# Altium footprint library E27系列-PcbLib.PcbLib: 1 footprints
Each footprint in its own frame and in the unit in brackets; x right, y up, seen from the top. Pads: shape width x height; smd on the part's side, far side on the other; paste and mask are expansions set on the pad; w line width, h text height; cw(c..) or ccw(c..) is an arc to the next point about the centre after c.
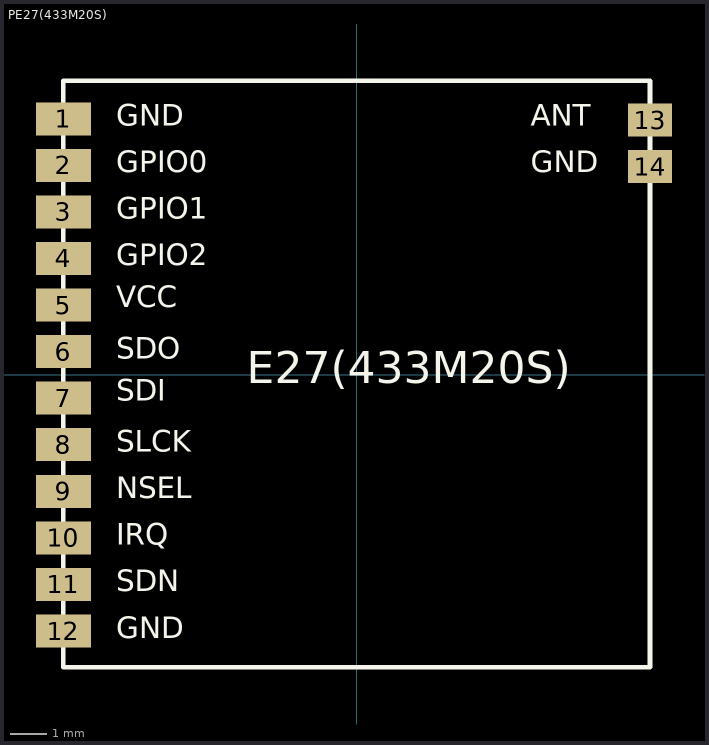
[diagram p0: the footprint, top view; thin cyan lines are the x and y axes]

## PE27(433M20S) [mm] "16mm*16mm*2.0mm-S"
pads (14):
  rect 1.5x0.9 smd: 1(-8.002,6.985) 2(-8.002,5.715) 3(-8.002,4.445) 4(-8.002,3.175) 5(-8.002,1.905) 6(-8.002,0.635) 7(-8.002,-0.635) 8(-8.002,-1.905) 9(-8.002,-3.175) 10(-8.002,-4.445) 11(-8.002,-5.715) 12(-8.002,-6.985)
  rect 1.2x0.9 smd: 13(8.002,6.947) 14(8.002,5.677)
Top Overlay:
  lines w0.127: -8.002,-7.976 7.998,-7.976 7.998,8.024 -8.002,8.024 -8.002,-7.976
  text "E27(433M20S)" at -3.005,-0.509 h1.5
  text "GND" at 4.742,5.333 h1
  text "ANT" at 4.742,6.603 h1
  text "GND" at -6.561,-7.367 h1
  text "SDI" at -6.561,-0.89 h1
  text "SDO" at -6.561,0.253 h1
  text "VCC" at -6.561,1.65 h1
  text "GPIO2" at -6.561,2.793 h1
  text "GPIO1" at -6.561,4.063 h1
  text "GND" at -6.561,6.603 h1
  text "GPIO0" at -6.561,5.333 h1
  text "SLCK" at -6.561,-2.287 h1
  text "NSEL" at -6.561,-3.557 h1
  text "IRQ" at -6.561,-4.827 h1
  text "SDN" at -6.561,-6.097 h1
